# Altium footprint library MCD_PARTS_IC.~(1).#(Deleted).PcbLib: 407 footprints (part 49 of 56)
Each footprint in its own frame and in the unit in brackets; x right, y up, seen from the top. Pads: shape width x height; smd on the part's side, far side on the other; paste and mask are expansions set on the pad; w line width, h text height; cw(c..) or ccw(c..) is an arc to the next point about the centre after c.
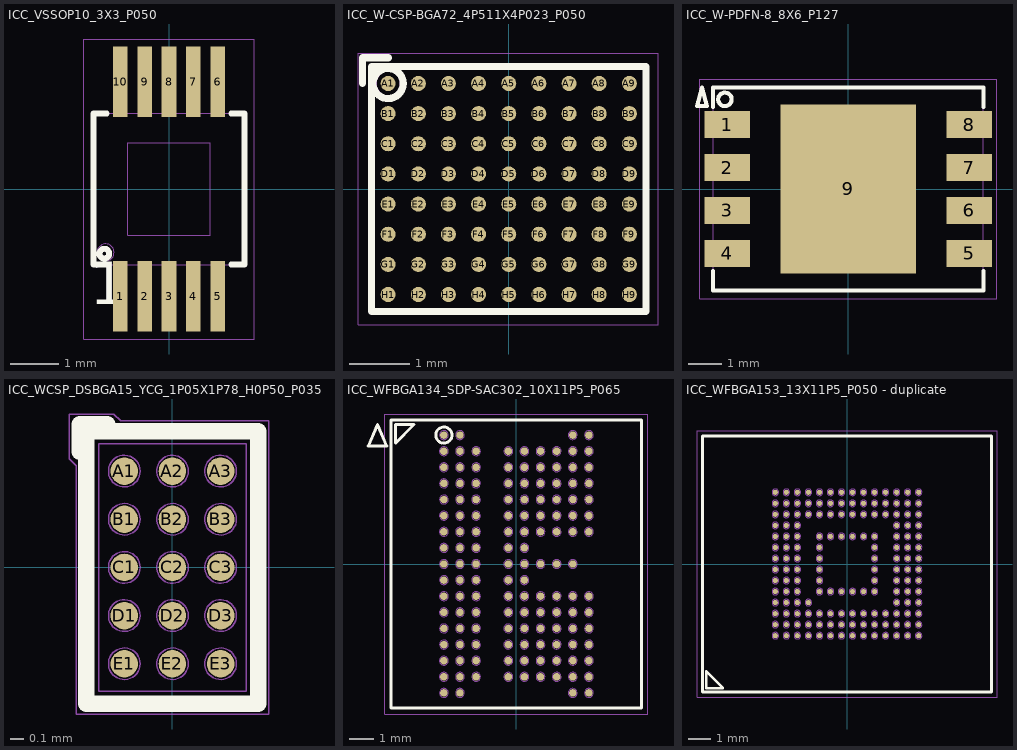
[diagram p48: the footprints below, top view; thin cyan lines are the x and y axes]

## ICC_VSSOP10_3X3_P050 [mm] "MCD-02208"
height 1.1
pads (10):
  rect 0.3x1.45 smd paste+0 mask+0.05: 1(-1,-2.2) 2(-0.5,-2.2) 3(0,-2.2) 4(0.5,-2.2) 5(1,-2.2) 6(1,2.2) 7(0.5,2.2) 8(0,2.2) 9(-0.5,2.2) 10(-1,2.2)
Top Overlay:
  circle w0.12: c-1.325,-1.325 r0.1
  lines w0.12: -1.275,-1.55 -1.55,-1.55 -1.55,1.55 -1.275,1.55 ; 1.275,-1.55 1.55,-1.55 1.55,1.55 1.275,1.55
  text "1" at -1.625,-2.65 h1.5
M14-Top Assembly:
  circle w0.01: c-1.3,-1.3 r0.175
  lines w0.01: -1.125,-1.55 -1.125,-2.5 -0.875,-2.5 -0.875,-1.55 ; -1.125,1.55 -1.125,2.5 -0.875,2.5 -0.875,1.55 ; -0.625,-1.55 -0.625,-2.5 -0.375,-2.5 -0.375,-1.55 ; -0.625,1.55 -0.625,2.5 -0.375,2.5 -0.375,1.55 ; -0.125,-1.55 -0.125,-2.5 0.125,-2.5 0.125,-1.55 ; -0.125,1.55 -0.125,2.5 0.125,2.5 0.125,1.55 ; 0.375,-1.55 0.375,-2.5 0.625,-2.5 0.625,-1.55 ; 0.375,1.55 0.375,2.5 0.625,2.5 0.625,1.55 ; 0.875,-1.55 0.875,-2.5 1.125,-2.5 1.125,-1.55 ; 0.875,1.55 0.875,2.5 1.125,2.5 1.125,1.55 ; -1.55,-1.55 1.55,-1.55 1.55,1.55 -1.55,1.55 -1.55,-1.55 ; -0.85,-0.95 0.85,-0.95 0.85,0.95 -0.85,0.95 -0.85,-0.95
  text "1" at -1.125,-2.35 h1
  text "5" at 0.8,-2.35 h1
  text "6" at 0.8,1.75 h1
  text "10" at -1.425,1.75 h1
  text "'.Designator'" at -2,-0.5 h0.75
M16-Top Courtyard:
  lines w0.01: -1.75,-3.075 -1.75,3.075 1.75,3.075 1.75,-3.075 -1.75,-3.075
3D body "User Library-DGS0010A.STEP": height 1.1, standoff 0, extent -1.5,-2.462 1.5,2.463
3D body: height 1.1, standoff 0, extent -1.549,-1.549 1.549,1.549

## ICC_W-CSP-BGA72_4P511X4P023_P050 [mm]
height 0.785
pads (72):
  round 0.25 smd mask+0.05: A1(-2,1.75) A2(-1.5,1.75) A3(-1,1.75) A4(-0.5,1.75) A5(0,1.75) A6(0.5,1.75) A7(1,1.75) A8(1.5,1.75) A9(2,1.75) B1(-2,1.25) B2(-1.5,1.25) B3(-1,1.25) B4(-0.5,1.25) B5(0,1.25) B6(0.5,1.25) B7(1,1.25) B8(1.5,1.25) B9(2,1.25) C1(-2,0.75) C2(-1.5,0.75) C3(-1,0.75) C4(-0.5,0.75) C5(0,0.75) C6(0.5,0.75) C7(1,0.75) C8(1.5,0.75) C9(2,0.75) D1(-2,0.25) D2(-1.5,0.25) D3(-1,0.25) D4(-0.5,0.25) D5(0,0.25) D6(0.5,0.25) D7(1,0.25) D8(1.5,0.25) D9(2,0.25) E1(-2,-0.25) E2(-1.5,-0.25) E3(-1,-0.25) E4(-0.5,-0.25) E5(0,-0.25) E6(0.5,-0.25) E7(1,-0.25) E8(1.5,-0.25) E9(2,-0.25) F1(-2,-0.75) F2(-1.5,-0.75) F3(-1,-0.75) F4(-0.5,-0.75) F5(0,-0.75) F6(0.5,-0.75) F7(1,-0.75) F8(1.5,-0.75) F9(2,-0.75) G1(-2,-1.25) G2(-1.5,-1.25) G3(-1,-1.25) G4(-0.5,-1.25) G5(0,-1.25) G6(0.5,-1.25) G7(1,-1.25) G8(1.5,-1.25) G9(2,-1.25) H1(-2,-1.75) H2(-1.5,-1.75) H3(-1,-1.75) H4(-0.5,-1.75) H5(0,-1.75) H6(0.5,-1.75) H7(1,-1.75) H8(1.5,-1.75) H9(2,-1.75)
Top Overlay:
  circle w0.12: c-2,1.75 r0.25
  lines w0.12: -2.425,1.75 -2.425,2.175 -2,2.175 ; -2.275,-2.031 2.275,-2.031 2.275,2.031 -2.275,2.031 -2.275,-2.031
M14-Top Assembly:
  circle w0.01: c-2,1.75 r0.2
  lines w0.01: -2.275,-2.031 2.275,-2.031 2.275,2.031 -2.275,2.031 -2.275,-2.031
  text "'.Designator'" at -2,-0.5 h0.75
M16-Top Courtyard:
  lines w0.01: -2.5,-2.25 -2.5,2.225 -2.5,2.25 -2.475,2.25 2.475,2.25 2.475,-2.25 -2.5,-2.25
3D body: height 0.78, standoff 0, extent -2.28,-2.036 2.28,2.036

## ICC_W-PDFN-8_8X6_P127 [mm]
height 0.8
pads (9):
  rect 1.35x0.8 smd mask+0.05: 1(-3.575,1.905) 2(-3.575,0.635) 3(-3.575,-0.635) 4(-3.575,-1.905) 5(3.575,-1.905) 6(3.575,-0.635) 7(3.575,0.635) 8(3.575,1.905)
  rect 4x5 smd mask+0.05: 9(0,0)
Top Overlay:
  circle w0.12: c-3.65,2.65 r0.2
  lines w0.12: -4,-2.425 -4,-3 4,-3 4,-2.425 ; -4,2.425 -4,3 4,3 4,2.425 ; -4.475,2.45 -4.325,3 -4.175,2.45 -4.475,2.45
M14-Top Assembly:
  circle w0.01: c-3.675,2.675 r0.2
  lines w0.01: -4,-2.16 -3.4,-2.16 -3.4,-1.65 -4,-1.65 ; -4,-0.89 -3.4,-0.89 -3.4,-0.38 -4,-0.38 ; -4,0.38 -3.4,0.38 -3.4,0.89 -4,0.89 ; -4,1.65 -3.4,1.65 -3.4,2.16 -4,2.16 ; 4,-2.16 3.4,-2.16 3.4,-1.65 4,-1.65 ; 4,-0.89 3.4,-0.89 3.4,-0.38 4,-0.38 ; 4,0.38 3.4,0.38 3.4,0.89 4,0.89 ; 4,1.65 3.4,1.65 3.4,2.16 4,2.16 ; -4,-3 -4,3 4,3 4,-3 -4,-3 ; -1.75,-2.2 -1.75,2.2 1.75,2.2 1.75,-2.2 -1.75,-2.2
  text "'.Designator'" at -2,-0.5 h0.75
  text "1" at -3.325,1.45 h1.5
  text "4" at -3.325,-2.375 h1.5
  text "5" at 2.675,-2.375 h1.5
  text "8" at 2.675,1.425 h1.5
M16-Top Courtyard:
  lines w0.01: -4.4,-3.25 4.4,-3.25 4.4,3.25 -4.4,3.25 -4.4,3.05 -4.4,-3.25
3D body: height 0.81, standoff 0.8, extent -3.697,1.901 -2.9,2.699
3D body: height 0.8, standoff 0, extent -4.005,-3.005 4.005,3.005

## ICC_WCSP_DSBGA15_YCG_1P05X1P78_H0P50_P035 [mm] "MCD-02471"
height 0.5
pads (15):
  round 0.2 smd mask+0.032: A1(-0.35,0.7) A2(0,0.7) A3(0.35,0.7) B1(-0.35,0.35) B2(0,0.35) B3(0.35,0.35) C1(-0.35,0) C2(0,0) C3(0.35,0) D1(-0.35,-0.35) D2(0,-0.35) D3(0.35,-0.35) E1(-0.35,-0.7) E2(0,-0.7) E3(0.35,-0.7)
Top Overlay:
  lines w0.12: -0.675,0.84 -0.675,1.04 -0.475,1.04 ; -0.475,0.99 -0.625,0.99 ; -0.625,0.99 0.625,0.99 0.625,-0.99 -0.625,-0.99 -0.625,0.99
Top Paste:
  drawing of 15 lines, arcs and shapes, not listed
M14-Top Assembly:
  circle w0.01: c0.35,-0.7 r0.115
  circle w0.01: c0,-0.7 r0.115
  circle w0.01: c-0.35,-0.7 r0.115
  circle w0.01: c0.35,-0.35 r0.115
  circle w0.01: c0,-0.35 r0.115
  circle w0.01: c-0.35,-0.35 r0.115
  circle w0.01: c0.35,0 r0.115
  circle w0.01: c0,0 r0.115
  circle w0.01: c-0.35,0 r0.115
  circle w0.01: c0.35,0.35 r0.115
  circle w0.01: c0,0.35 r0.115
  circle w0.01: c-0.35,0.35 r0.115
  circle w0.01: c0.35,0.7 r0.115
  circle w0.01: c0,0.7 r0.115
  circle w0.01: c-0.35,0.7 r0.115
  lines w0.01: -0.535,-0.9 -0.535,0.9 -0.466,0.9 0.535,0.9 0.535,-0.9 -0.535,-0.9
  text "E3" at 0.227,-0.777 h0.25
  text "E2" at -0.122,-0.777 h0.25
  text "E1" at -0.457,-0.777 h0.25
  text "D3" at 0.221,-0.427 h0.25
  text "D2" at -0.129,-0.427 h0.25
  text "D1" at -0.464,-0.427 h0.25
  text "C3" at 0.218,-0.079 h0.25
  text "C2" at -0.132,-0.079 h0.25
  text "C1" at -0.467,-0.079 h0.25
  text "B3" at 0.226,0.273 h0.25
  text "B2" at -0.123,0.273 h0.25
  text "B1" at -0.458,0.273 h0.25
  text "A3" at 0.218,0.623 h0.25
  text "A2" at -0.131,0.623 h0.25
  text "A1" at -0.467,0.623 h0.25
  text "'.Designator'" at -2,-0.5 h0.75
M16-Top Courtyard:
  lines w0.01: -0.75,0.79 -0.75,1.115 -0.425,1.115 -0.375,1.065 0.7,1.065 0.7,-1.065 -0.7,-1.065 -0.7,0.74 -0.75,0.79
3D body: height 0.24, standoff -0.02, extent 0.224,-0.828 0.476,-0.572
3D body: height 0.24, standoff -0.02, extent -0.126,-0.828 0.126,-0.572
3D body: height 0.24, standoff -0.02, extent -0.476,-0.828 -0.224,-0.572
3D body: height 0.24, standoff -0.02, extent 0.224,-0.478 0.476,-0.222
3D body: height 0.24, standoff -0.02, extent -0.126,-0.478 0.126,-0.222
3D body: height 0.24, standoff -0.02, extent -0.476,-0.478 -0.224,-0.222
3D body: height 0.24, standoff -0.02, extent 0.224,-0.128 0.476,0.128
3D body: height 0.24, standoff -0.02, extent -0.126,-0.128 0.126,0.128
3D body: height 0.24, standoff -0.02, extent -0.476,-0.128 -0.224,0.128
3D body: height 0.24, standoff -0.02, extent 0.224,0.222 0.476,0.478
3D body: height 0.24, standoff -0.02, extent -0.126,0.222 0.126,0.478
3D body: height 0.24, standoff -0.02, extent -0.476,0.222 -0.224,0.478
3D body: height 0.24, standoff -0.02, extent 0.224,0.572 0.476,0.828
3D body: height 0.24, standoff -0.02, extent -0.126,0.572 0.126,0.828
3D body: height 0.51, standoff 0.5, extent -0.535,0.5 -0.3,0.9
3D body: height 0.24, standoff -0.02, extent -0.476,0.572 -0.224,0.828
3D body: height 0.5, standoff 0.13, extent -0.535,-0.9 0.535,0.9

## ICC_WFBGA134_SDP-SAC302_10X11P5_P065 [mm] "IPC"
height 0.75
pads (134):
  round 0.3 smd mask+0.05: A1(-2.925,5.2) A2(-2.275,5.2) A9(2.275,5.2) A10(2.925,5.2) B1(-2.925,4.55) B2(-2.275,4.55) B3(-1.625,4.55) B5(-0.325,4.55) B6(0.325,4.55) B7(0.975,4.55) B8(1.625,4.55) B9(2.275,4.55) B10(2.925,4.55) C1(-2.925,3.9) C2(-2.275,3.9) C3(-1.625,3.9) C5(-0.325,3.9) C6(0.325,3.9) C7(0.975,3.9) C8(1.625,3.9) C9(2.275,3.9) C10(2.925,3.9) D1(-2.925,3.25) D2(-2.275,3.25) D3(-1.625,3.25) D5(-0.325,3.25) D6(0.325,3.25) D7(0.975,3.25) D8(1.625,3.25) D9(2.275,3.25) D10(2.925,3.25) E1(-2.925,2.6) E2(-2.275,2.6) E3(-1.625,2.6) E5(-0.325,2.6) E6(0.325,2.6) E7(0.975,2.6) E8(1.625,2.6) E9(2.275,2.6) E10(2.925,2.6) F1(-2.925,1.95) F2(-2.275,1.95) F3(-1.625,1.95) F5(-0.325,1.95) F6(0.325,1.95) F7(0.975,1.95) F8(1.625,1.95) F9(2.275,1.95) F10(2.925,1.95) G1(-2.925,1.3) G2(-2.275,1.3) G3(-1.625,1.3) G5(-0.325,1.3) G6(0.325,1.3) G7(0.975,1.3) G8(1.625,1.3) G9(2.275,1.3) G10(2.925,1.3) H1(-2.925,0.65) H2(-2.275,0.65) H3(-1.625,0.65) H5(-0.325,0.65) H6(0.325,0.65) J1(-2.925,0) J2(-2.275,0) J3(-1.625,0) J5(-0.325,0) J6(0.325,0) J7(0.975,0) J8(1.625,0) J9(2.275,0) K1(-2.925,-0.65) K2(-2.275,-0.65) K3(-1.625,-0.65) K5(-0.325,-0.65) K6(0.325,-0.65) L1(-2.925,-1.3) L2(-2.275,-1.3) L3(-1.625,-1.3) L5(-0.325,-1.3) L6(0.325,-1.3) L7(0.975,-1.3) L8(1.625,-1.3) L9(2.275,-1.3) L10(2.925,-1.3) M1(-2.925,-1.95) M2(-2.275,-1.95) M3(-1.625,-1.95) M5(-0.325,-1.95) M6(0.325,-1.95) M7(0.975,-1.95) M8(1.625,-1.95) M9(2.275,-1.95) M10(2.925,-1.95) N1(-2.925,-2.6) N2(-2.275,-2.6) N3(-1.625,-2.6) N5(-0.325,-2.6) N6(0.325,-2.6) N7(0.975,-2.6) N8(1.625,-2.6) N9(2.275,-2.6) N10(2.925,-2.6) P1(-2.925,-3.25) P2(-2.275,-3.25) P3(-1.625,-3.25) P5(-0.325,-3.25) P6(0.325,-3.25) P7(0.975,-3.25) P8(1.625,-3.25) P9(2.275,-3.25) P10(2.925,-3.25) R1(-2.925,-3.9) R2(-2.275,-3.9) R3(-1.625,-3.9) R5(-0.325,-3.9) R6(0.325,-3.9) R7(0.975,-3.9) R8(1.625,-3.9) R9(2.275,-3.9) R10(2.925,-3.9) T1(-2.925,-4.55) T2(-2.275,-4.55) T3(-1.625,-4.55) T5(-0.325,-4.55) T6(0.325,-4.55) T7(0.975,-4.55) T8(1.625,-4.55) T9(2.275,-4.55) T10(2.925,-4.55) U1(-2.925,-5.2) U2(-2.275,-5.2) U9(2.275,-5.2) U10(2.925,-5.2)
Top Overlay:
  circle w0.12: c-2.925,5.2 r0.325
  lines w0.12: -4.125,5.625 -4.875,4.875 -4.875,5.625 -4.125,5.625 ; -4.125,5.625 -4.125,5.625 ; -5.975,4.75 -5.225,4.75 -5.6,5.625 -5.975,4.75 ; -5.05,-5.8 5.05,-5.8 5.05,5.8 -5.05,5.8 -5.05,-5.8
M14-Top Assembly:
  circle w0.01: c-2.925,-5.2 r0.18
  circle w0.01: c-2.275,-5.2 r0.18
  circle w0.01: c2.275,-5.2 r0.18
  circle w0.01: c2.925,-5.2 r0.18
  circle w0.01: c-2.925,-4.55 r0.18
  circle w0.01: c-2.275,-4.55 r0.18
  circle w0.01: c-1.625,-4.55 r0.18
  circle w0.01: c-0.325,-4.55 r0.18
  circle w0.01: c0.325,-4.55 r0.18
  circle w0.01: c0.975,-4.55 r0.18
  circle w0.01: c1.625,-4.55 r0.18
  circle w0.01: c2.275,-4.55 r0.18
  circle w0.01: c2.925,-4.55 r0.18
  circle w0.01: c-2.925,-3.9 r0.18
  circle w0.01: c-2.275,-3.9 r0.18
  circle w0.01: c-1.625,-3.9 r0.18
  circle w0.01: c-0.325,-3.9 r0.18
  circle w0.01: c0.325,-3.9 r0.18
  circle w0.01: c0.975,-3.9 r0.18
  circle w0.01: c1.625,-3.9 r0.18
  circle w0.01: c2.275,-3.9 r0.18
  circle w0.01: c2.925,-3.9 r0.18
  circle w0.01: c-2.925,-3.25 r0.18
  circle w0.01: c-2.275,-3.25 r0.18
  circle w0.01: c-1.625,-3.25 r0.18
  circle w0.01: c-0.325,-3.25 r0.18
  circle w0.01: c0.325,-3.25 r0.18
  circle w0.01: c0.975,-3.25 r0.18
  circle w0.01: c1.625,-3.25 r0.18
  circle w0.01: c2.275,-3.25 r0.18
  circle w0.01: c2.925,-3.25 r0.18
  circle w0.01: c-2.925,-2.6 r0.18
  circle w0.01: c-2.275,-2.6 r0.18
  circle w0.01: c-1.625,-2.6 r0.18
  circle w0.01: c-0.325,-2.6 r0.18
  circle w0.01: c0.325,-2.6 r0.18
  circle w0.01: c0.975,-2.6 r0.18
  circle w0.01: c1.625,-2.6 r0.18
  circle w0.01: c2.275,-2.6 r0.18
  circle w0.01: c2.925,-2.6 r0.18
  circle w0.01: c-2.925,-1.95 r0.18
  circle w0.01: c-2.275,-1.95 r0.18
  circle w0.01: c-1.625,-1.95 r0.18
  circle w0.01: c-0.325,-1.95 r0.18
  circle w0.01: c0.325,-1.95 r0.18
  circle w0.01: c0.975,-1.95 r0.18
  circle w0.01: c1.625,-1.95 r0.18
  circle w0.01: c2.275,-1.95 r0.18
  circle w0.01: c2.925,-1.95 r0.18
  circle w0.01: c-2.925,-1.3 r0.18
  circle w0.01: c-2.275,-1.3 r0.18
  circle w0.01: c-1.625,-1.3 r0.18
  circle w0.01: c-0.325,-1.3 r0.18
  circle w0.01: c0.325,-1.3 r0.18
  circle w0.01: c0.975,-1.3 r0.18
  circle w0.01: c1.625,-1.3 r0.18
  circle w0.01: c2.275,-1.3 r0.18
  circle w0.01: c2.925,-1.3 r0.18
  circle w0.01: c-2.925,-0.65 r0.18
  circle w0.01: c-2.275,-0.65 r0.18
  circle w0.01: c-1.625,-0.65 r0.18
  circle w0.01: c-0.325,-0.65 r0.18
  circle w0.01: c0.325,-0.65 r0.18
  circle w0.01: c-2.925,0 r0.18
  circle w0.01: c-2.275,0 r0.18
  circle w0.01: c-1.625,0 r0.18
  circle w0.01: c-0.325,0 r0.18
  circle w0.01: c0.325,0 r0.18
  circle w0.01: c0.975,0 r0.18
  circle w0.01: c1.625,0 r0.18
  circle w0.01: c2.275,0 r0.18
  circle w0.01: c-2.925,0.65 r0.18
  circle w0.01: c-2.275,0.65 r0.18
  circle w0.01: c-1.625,0.65 r0.18
  circle w0.01: c-0.325,0.65 r0.18
  circle w0.01: c0.325,0.65 r0.18
  circle w0.01: c-2.925,1.3 r0.18
  circle w0.01: c-2.275,1.3 r0.18
  circle w0.01: c-1.625,1.3 r0.18
  circle w0.01: c-0.325,1.3 r0.18
  circle w0.01: c0.325,1.3 r0.18
  circle w0.01: c0.975,1.3 r0.18
  circle w0.01: c1.625,1.3 r0.18
  circle w0.01: c2.275,1.3 r0.18
  circle w0.01: c2.925,1.3 r0.18
  circle w0.01: c-2.925,1.95 r0.18
  circle w0.01: c-2.275,1.95 r0.18
  circle w0.01: c-1.625,1.95 r0.18
  circle w0.01: c-0.325,1.95 r0.18
  circle w0.01: c0.325,1.95 r0.18
  circle w0.01: c0.975,1.95 r0.18
  circle w0.01: c1.625,1.95 r0.18
  circle w0.01: c2.275,1.95 r0.18
  circle w0.01: c2.925,1.95 r0.18
  circle w0.01: c-2.925,2.6 r0.18
  circle w0.01: c-2.275,2.6 r0.18
  circle w0.01: c-1.625,2.6 r0.18
  circle w0.01: c-0.325,2.6 r0.18
  circle w0.01: c0.325,2.6 r0.18
  circle w0.01: c0.975,2.6 r0.18
  circle w0.01: c1.625,2.6 r0.18
  circle w0.01: c2.275,2.6 r0.18
  circle w0.01: c2.925,2.6 r0.18
  circle w0.01: c-2.925,3.25 r0.18
  circle w0.01: c-2.275,3.25 r0.18
  circle w0.01: c-1.625,3.25 r0.18
  circle w0.01: c-0.325,3.25 r0.18
  circle w0.01: c0.325,3.25 r0.18
  circle w0.01: c0.975,3.25 r0.18
  circle w0.01: c1.625,3.25 r0.18
  circle w0.01: c2.275,3.25 r0.18
  circle w0.01: c2.925,3.25 r0.18
  circle w0.01: c-2.925,3.9 r0.18
  circle w0.01: c-2.275,3.9 r0.18
  circle w0.01: c-1.625,3.9 r0.18
  circle w0.01: c-0.325,3.9 r0.18
  circle w0.01: c0.325,3.9 r0.18
  circle w0.01: c0.975,3.9 r0.18
  circle w0.01: c1.625,3.9 r0.18
  circle w0.01: c2.275,3.9 r0.18
  circle w0.01: c2.925,3.9 r0.18
  circle w0.01: c2.925,4.55 r0.18
  circle w0.01: c2.275,4.55 r0.18
  circle w0.01: c1.625,4.55 r0.18
  circle w0.01: c0.975,4.55 r0.18
  circle w0.01: c0.325,4.55 r0.18
  circle w0.01: c-0.325,4.55 r0.18
  circle w0.01: c-1.625,4.55 r0.18
  circle w0.01: c-2.275,4.55 r0.18
  circle w0.01: c-2.925,4.55 r0.18
  circle w0.01: c2.925,5.2 r0.18
  circle w0.01: c2.275,5.2 r0.18
  circle w0.01: c-2.275,5.2 r0.18
  circle w0.01: c-2.925,5.2 r0.18
  lines w0.01: -5.05,-5.8 -5.05,5.8 5.05,5.8 5.05,-5.8 -5.05,-5.8
  text "A" at -3.608,5.038 h0.5
  text "B" at -3.608,4.387 h0.5
  text "C" at -3.608,3.738 h0.5
  text "D" at -3.608,3.087 h0.5
  text "E" at -3.608,2.438 h0.5
  text "F" at -3.608,1.787 h0.5
  text "G" at -3.608,1.138 h0.5
  text "H" at -3.608,0.487 h0.5
  text "J" at -3.608,-0.162 h0.5
  text "K" at -3.608,-0.813 h0.5
  text "L" at -3.608,-1.462 h0.5
  text "M" at -3.608,-2.113 h0.5
  text "N" at -3.608,-2.762 h0.5
  text "P" at -3.608,-3.413 h0.5
  text "R" at -3.608,-4.062 h0.5
  text "T" at -3.608,-4.713 h0.5
  text "U" at -3.608,-5.362 h0.5
  text "1" at -3.023,5.427 h0.5
  text "2" at -2.372,5.427 h0.5
  text "3" at -1.723,5.427 h0.5
  text "4" at -1.072,5.427 h0.5
  text "5" at -0.423,5.427 h0.5
  text "6" at 0.228,5.427 h0.5
  text "7" at 0.877,5.427 h0.5
  text "8" at 1.528,5.427 h0.5
  text "9" at 2.177,5.427 h0.5
  text "10" at 2.698,5.427 h0.5
  text "'.Designator'" at 0.5,0 h0.75
M16-Top Courtyard:
  lines w0.01: -5.3,-6.05 5.3,-6.05 5.3,6.05 -5.3,6.05 -5.3,-6.05
3D body: height 0.75, standoff 0.28, extent -5.05,-5.8 5.05,5.8
3D body: height 0.34, standoff -0.02, extent 2.754,5.023 3.105,5.377
3D body: height 0.34, standoff -0.02, extent 2.104,5.023 2.455,5.377
3D body: height 0.34, standoff -0.02, extent -2.446,5.023 -2.095,5.377
3D body: height 0.34, standoff -0.02, extent -3.096,5.023 -2.745,5.377
3D body: height 0.34, standoff -0.02, extent -3.096,4.373 -2.745,4.727
3D body: height 0.34, standoff -0.02, extent -2.446,4.373 -2.095,4.727
3D body: height 0.34, standoff -0.02, extent -1.796,4.373 -1.445,4.727
3D body: height 0.34, standoff -0.02, extent -0.496,4.373 -0.145,4.727
3D body: height 0.34, standoff -0.02, extent 0.154,4.373 0.505,4.727
3D body: height 0.34, standoff -0.02, extent 0.804,4.373 1.155,4.727
3D body: height 0.34, standoff -0.02, extent 1.454,4.373 1.805,4.727
3D body: height 0.34, standoff -0.02, extent 2.104,4.373 2.455,4.727
3D body: height 0.34, standoff -0.02, extent 2.754,4.373 3.105,4.727
3D body: height 0.34, standoff -0.02, extent 2.754,3.723 3.105,4.077
3D body: height 0.34, standoff -0.02, extent 2.104,3.723 2.455,4.077
3D body: height 0.34, standoff -0.02, extent 1.454,3.723 1.805,4.077
3D body: height 0.34, standoff -0.02, extent 0.804,3.723 1.155,4.077
3D body: height 0.34, standoff -0.02, extent 0.154,3.723 0.505,4.077
3D body: height 0.34, standoff -0.02, extent -0.496,3.723 -0.145,4.077
3D body: height 0.34, standoff -0.02, extent -1.796,3.723 -1.445,4.077
3D body: height 0.34, standoff -0.02, extent -2.446,3.723 -2.095,4.077
3D body: height 0.34, standoff -0.02, extent -3.096,3.723 -2.745,4.077
3D body: height 0.34, standoff -0.02, extent 2.754,3.073 3.105,3.427
3D body: height 0.34, standoff -0.02, extent 2.104,3.073 2.455,3.427
3D body: height 0.34, standoff -0.02, extent 1.454,3.073 1.805,3.427
3D body: height 0.34, standoff -0.02, extent 0.804,3.073 1.155,3.427
3D body: height 0.34, standoff -0.02, extent 0.154,3.073 0.505,3.427
3D body: height 0.34, standoff -0.02, extent -0.496,3.073 -0.145,3.427
3D body: height 0.34, standoff -0.02, extent -1.796,3.073 -1.445,3.427
3D body: height 0.34, standoff -0.02, extent -2.446,3.073 -2.095,3.427
3D body: height 0.34, standoff -0.02, extent -3.096,3.073 -2.745,3.427
3D body: height 0.34, standoff -0.02, extent 2.754,2.423 3.105,2.777
3D body: height 0.34, standoff -0.02, extent 2.104,2.423 2.455,2.777
3D body: height 0.34, standoff -0.02, extent 1.454,2.423 1.805,2.777
3D body: height 0.34, standoff -0.02, extent 0.804,2.423 1.155,2.777
3D body: height 0.34, standoff -0.02, extent 0.154,2.423 0.505,2.777
3D body: height 0.34, standoff -0.02, extent -0.496,2.423 -0.145,2.777
3D body: height 0.34, standoff -0.02, extent -1.796,2.423 -1.445,2.777
3D body: height 0.34, standoff -0.02, extent -2.446,2.423 -2.095,2.777
3D body: height 0.34, standoff -0.02, extent -3.096,2.423 -2.745,2.777
3D body: height 0.34, standoff -0.02, extent 2.754,1.773 3.105,2.127
3D body: height 0.34, standoff -0.02, extent 2.104,1.773 2.455,2.127
3D body: height 0.34, standoff -0.02, extent 1.454,1.773 1.805,2.127
3D body: height 0.34, standoff -0.02, extent 0.804,1.773 1.155,2.127
3D body: height 0.34, standoff -0.02, extent 0.154,1.773 0.505,2.127
3D body: height 0.34, standoff -0.02, extent -0.496,1.773 -0.145,2.127
3D body: height 0.34, standoff -0.02, extent -1.796,1.773 -1.445,2.127
3D body: height 0.34, standoff -0.02, extent -2.446,1.773 -2.095,2.127
3D body: height 0.34, standoff -0.02, extent -3.096,1.773 -2.745,2.127
3D body: height 0.34, standoff -0.02, extent 2.754,1.123 3.105,1.477
3D body: height 0.34, standoff -0.02, extent 2.104,1.123 2.455,1.477
3D body: height 0.34, standoff -0.02, extent 1.454,1.123 1.805,1.477
3D body: height 0.34, standoff -0.02, extent 0.804,1.123 1.155,1.477
3D body: height 0.34, standoff -0.02, extent 0.154,1.123 0.505,1.477
3D body: height 0.34, standoff -0.02, extent -0.496,1.123 -0.145,1.477
3D body: height 0.34, standoff -0.02, extent -1.796,1.123 -1.445,1.477
3D body: height 0.34, standoff -0.02, extent -2.446,1.123 -2.095,1.477
3D body: height 0.34, standoff -0.02, extent -3.096,1.123 -2.745,1.477
3D body: height 0.34, standoff -0.02, extent 2.754,-1.477 3.105,-1.123
3D body: height 0.34, standoff -0.02, extent 2.104,-1.477 2.455,-1.123
3D body: height 0.34, standoff -0.02, extent 1.454,-1.477 1.805,-1.123
3D body: height 0.34, standoff -0.02, extent 0.804,-1.477 1.155,-1.123
3D body: height 0.34, standoff -0.02, extent 0.154,-1.477 0.505,-1.123
3D body: height 0.34, standoff -0.02, extent -0.496,-1.477 -0.145,-1.123
3D body: height 0.34, standoff -0.02, extent -1.796,-1.477 -1.445,-1.123
3D body: height 0.34, standoff -0.02, extent -2.446,-1.477 -2.095,-1.123
3D body: height 0.34, standoff -0.02, extent -3.096,-1.477 -2.745,-1.123
3D body: height 0.34, standoff -0.02, extent 2.754,-2.127 3.105,-1.773
3D body: height 0.34, standoff -0.02, extent 2.104,-2.127 2.455,-1.773
3D body: height 0.34, standoff -0.02, extent 1.454,-2.127 1.805,-1.773
3D body: height 0.34, standoff -0.02, extent 0.804,-2.127 1.155,-1.773
3D body: height 0.34, standoff -0.02, extent 0.154,-2.127 0.505,-1.773
3D body: height 0.34, standoff -0.02, extent -0.496,-2.127 -0.145,-1.773
3D body: height 0.34, standoff -0.02, extent -1.796,-2.127 -1.445,-1.773
3D body: height 0.34, standoff -0.02, extent -2.446,-2.127 -2.095,-1.773
3D body: height 0.34, standoff -0.02, extent -3.096,-2.127 -2.745,-1.773
3D body: height 0.34, standoff -0.02, extent 2.754,-2.777 3.105,-2.423
3D body: height 0.34, standoff -0.02, extent 2.104,-2.777 2.455,-2.423
3D body: height 0.34, standoff -0.02, extent 1.454,-2.777 1.805,-2.423
3D body: height 0.34, standoff -0.02, extent 0.804,-2.777 1.155,-2.423
3D body: height 0.34, standoff -0.02, extent 0.154,-2.777 0.505,-2.423
3D body: height 0.34, standoff -0.02, extent -0.496,-2.777 -0.145,-2.423
3D body: height 0.34, standoff -0.02, extent -1.796,-2.777 -1.445,-2.423
3D body: height 0.34, standoff -0.02, extent -2.446,-2.777 -2.095,-2.423
3D body: height 0.34, standoff -0.02, extent -3.096,-2.777 -2.745,-2.423
3D body: height 0.34, standoff -0.02, extent 2.754,-3.427 3.105,-3.073
3D body: height 0.34, standoff -0.02, extent 2.104,-3.427 2.455,-3.073
3D body: height 0.34, standoff -0.02, extent 1.454,-3.427 1.805,-3.073
3D body: height 0.34, standoff -0.02, extent 0.804,-3.427 1.155,-3.073
3D body: height 0.34, standoff -0.02, extent 0.154,-3.427 0.505,-3.073
3D body: height 0.34, standoff -0.02, extent -0.496,-3.427 -0.145,-3.073
3D body: height 0.34, standoff -0.02, extent -1.796,-3.427 -1.445,-3.073
3D body: height 0.34, standoff -0.02, extent -2.446,-3.427 -2.095,-3.073
3D body: height 0.34, standoff -0.02, extent -3.096,-3.427 -2.745,-3.073
3D body: height 0.34, standoff -0.02, extent 2.754,-4.077 3.105,-3.723
3D body: height 0.34, standoff -0.02, extent 2.104,-4.077 2.455,-3.723
3D body: height 0.34, standoff -0.02, extent 1.454,-4.077 1.805,-3.723
3D body: height 0.34, standoff -0.02, extent 0.804,-4.077 1.155,-3.723
3D body: height 0.34, standoff -0.02, extent 0.154,-4.077 0.505,-3.723
3D body: height 0.34, standoff -0.02, extent -0.496,-4.077 -0.145,-3.723
3D body: height 0.34, standoff -0.02, extent -1.796,-4.077 -1.445,-3.723
3D body: height 0.34, standoff -0.02, extent -2.446,-4.077 -2.095,-3.723
3D body: height 0.34, standoff -0.02, extent -3.096,-4.077 -2.745,-3.723
3D body: height 0.34, standoff -0.02, extent 2.754,-4.727 3.105,-4.373
3D body: height 0.34, standoff -0.02, extent 2.104,-4.727 2.455,-4.373
3D body: height 0.34, standoff -0.02, extent 1.454,-4.727 1.805,-4.373
3D body: height 0.34, standoff -0.02, extent 0.804,-4.727 1.155,-4.373
3D body: height 0.34, standoff -0.02, extent 0.154,-4.727 0.505,-4.373
3D body: height 0.34, standoff -0.02, extent -0.496,-4.727 -0.145,-4.373
3D body: height 0.34, standoff -0.02, extent -1.796,-4.727 -1.445,-4.373
3D body: height 0.34, standoff -0.02, extent -2.446,-4.727 -2.095,-4.373
3D body: height 0.34, standoff -0.02, extent -3.096,-4.727 -2.745,-4.373
3D body: height 0.34, standoff -0.02, extent -3.096,0.473 -2.745,0.827
3D body: height 0.34, standoff -0.02, extent -2.446,0.473 -2.095,0.827
3D body: height 0.34, standoff -0.02, extent -1.796,0.473 -1.445,0.827
3D body: height 0.34, standoff -0.02, extent -0.496,0.473 -0.145,0.827
3D body: height 0.34, standoff -0.02, extent 0.154,0.473 0.505,0.827
3D body: height 0.34, standoff -0.02, extent -3.096,-0.177 -2.745,0.177
3D body: height 0.34, standoff -0.02, extent -2.446,-0.177 -2.095,0.177
3D body: height 0.34, standoff -0.02, extent -1.796,-0.177 -1.445,0.177
3D body: height 0.34, standoff -0.02, extent -0.496,-0.177 -0.145,0.177
3D body: height 0.34, standoff -0.02, extent 0.154,-0.177 0.505,0.177
3D body: height 0.34, standoff -0.02, extent 0.804,-0.177 1.155,0.177
3D body: height 0.34, standoff -0.02, extent 1.454,-0.177 1.805,0.177
3D body: height 0.34, standoff -0.02, extent 2.104,-0.177 2.455,0.177
3D body: height 0.34, standoff -0.02, extent -3.096,-0.827 -2.745,-0.473
3D body: height 0.34, standoff -0.02, extent -2.446,-0.827 -2.095,-0.473
3D body: height 0.34, standoff -0.02, extent -1.796,-0.827 -1.445,-0.473
3D body: height 0.34, standoff -0.02, extent -0.496,-0.827 -0.145,-0.473
3D body: height 0.34, standoff -0.02, extent 0.154,-0.827 0.505,-0.473
3D body: height 0.34, standoff -0.02, extent -3.096,-5.377 -2.745,-5.023
3D body: height 0.34, standoff -0.02, extent -2.446,-5.377 -2.095,-5.023
3D body: height 0.34, standoff -0.02, extent 2.104,-5.377 2.455,-5.023
3D body: height 0.34, standoff -0.02, extent 2.754,-5.377 3.105,-5.023
3D body: height 0.76, standoff 0.75, extent -4.747,4.901 -4.15,5.5

## ICC_WFBGA153_13X11P5_P050 - duplicate [mm] "MCD-04155"
height 0.8
pads (153):
  round 0.23 smd paste+0.025 mask+0.05: A1(-3.25,-3.25) A2(-3.25,-2.75) A3(-3.25,-2.25) A4(-3.25,-1.75) A5(-3.25,-1.25) A6(-3.25,-0.75) A7(-3.25,-0.25) A8(-3.25,0.25) A9(-3.25,0.75) A10(-3.25,1.25) A11(-3.25,1.75) A12(-3.25,2.25) A13(-3.25,2.75) A14(-3.25,3.25) B1(-2.75,-3.25) B2(-2.75,-2.75) B3(-2.75,-2.25) B4(-2.75,-1.75) B5(-2.75,-1.25) B6(-2.75,-0.75) B7(-2.75,-0.25) B8(-2.75,0.25) B9(-2.75,0.75) B10(-2.75,1.25) B11(-2.75,1.75) B12(-2.75,2.25) B13(-2.75,2.75) B14(-2.75,3.25) C1(-2.25,-3.25) C2(-2.25,-2.75) C3(-2.25,-2.25) C4(-2.25,-1.75) C5(-2.25,-1.25) C6(-2.25,-0.75) C7(-2.25,-0.25) C8(-2.25,0.25) C9(-2.25,0.75) C10(-2.25,1.25) C11(-2.25,1.75) C12(-2.25,2.25) C13(-2.25,2.75) C14(-2.25,3.25) D1(-1.75,-3.25) D2(-1.75,-2.75) D3(-1.75,-2.25) D4(-1.75,-1.75) D12(-1.75,2.25) D13(-1.75,2.75) D14(-1.75,3.25) E1(-1.25,-3.25) E2(-1.25,-2.75) E3(-1.25,-2.25) E5(-1.25,-1.25) E6(-1.25,-0.75) E7(-1.25,-0.25) E8(-1.25,0.25) E9(-1.25,0.75) E10(-1.25,1.25) E12(-1.25,2.25) E13(-1.25,2.75) E14(-1.25,3.25) F1(-0.75,-3.25) F2(-0.75,-2.75) F3(-0.75,-2.25) F5(-0.75,-1.25) F10(-0.75,1.25) F12(-0.75,2.25) F13(-0.75,2.75) F14(-0.75,3.25) G1(-0.25,-3.25) G2(-0.25,-2.75) G3(-0.25,-2.25) G5(-0.25,-1.25) G10(-0.25,1.25) G12(-0.25,2.25) G13(-0.25,2.75) G14(-0.25,3.25) H1(0.25,-3.25) H2(0.25,-2.75) H3(0.25,-2.25) H5(0.25,-1.25) H10(0.25,1.25) H12(0.25,2.25) H13(0.25,2.75) H14(0.25,3.25) J1(0.75,-3.25) J2(0.75,-2.75) J3(0.75,-2.25) J5(0.75,-1.25) J10(0.75,1.25) J12(0.75,2.25) J13(0.75,2.75) J14(0.75,3.25) K1(1.25,-3.25) K2(1.25,-2.75) K3(1.25,-2.25) K5(1.25,-1.25) K6(1.25,-0.75) K7(1.25,-0.25) K8(1.25,0.25) K9(1.25,0.75) K10(1.25,1.25) K12(1.25,2.25) K13(1.25,2.75) K14(1.25,3.25) L1(1.75,-3.25) L2(1.75,-2.75) L3(1.75,-2.25) L12(1.75,2.25) L13(1.75,2.75) L14(1.75,3.25) M1(2.25,-3.25) M2(2.25,-2.75) M3(2.25,-2.25) M4(2.25,-1.75) M5(2.25,-1.25) M6(2.25,-0.75) M7(2.25,-0.25) M8(2.25,0.25) M9(2.25,0.75) M10(2.25,1.25) M11(2.25,1.75) M12(2.25,2.25) M13(2.25,2.75) M14(2.25,3.25) N1(2.75,-3.25) N2(2.75,-2.75) N3(2.75,-2.25) N4(2.75,-1.75) N5(2.75,-1.25) N6(2.75,-0.75) N7(2.75,-0.25) N8(2.75,0.25) N9(2.75,0.75) N10(2.75,1.25) N11(2.75,1.75) N12(2.75,2.25) N13(2.75,2.75) N14(2.75,3.25) P1(3.25,-3.25) P2(3.25,-2.75) P3(3.25,-2.25) P4(3.25,-1.75) P5(3.25,-1.25) P6(3.25,-0.75) P7(3.25,-0.25) P8(3.25,0.25) P9(3.25,0.75) P10(3.25,1.25) P11(3.25,1.75) P12(3.25,2.25) P13(3.25,2.75) P14(3.25,3.25)
Top Overlay:
  lines w0.12: -6.375,-4.875 -6.375,-5.625 -5.625,-5.625 -6.375,-4.875 ; -6.375,-4.875 -6.375,-4.875 ; -6.55,-5.8 -6.55,5.8 6.55,5.8 6.55,-5.8 -6.55,-5.8
M14-Top Assembly:
  drawing of 157 lines, arcs and shapes, not listed
  text "A1" at -4.125,-3.75 h0.5
  text "'.Designator'" at 0,0 h0.75
M16-Top Courtyard:
  lines w0.01: -6.8,-6.05 -6.8,6.05 6.8,6.05 6.8,-6.05 -6.8,-6.05
3D body: height 0.8, standoff 0.28, extent -6.55,-5.8 6.55,5.8
3D body: height 0.31, standoff 0.01, extent -3.4,-3.4 -3.1,-3.1
3D body: height 0.31, standoff 0.01, extent -2.9,-3.4 -2.6,-3.1
3D body: height 0.31, standoff 0.01, extent -2.4,-3.4 -2.1,-3.1
3D body: height 0.31, standoff 0.01, extent -1.9,-3.4 -1.6,-3.1
3D body: height 0.31, standoff 0.01, extent -1.4,-3.4 -1.1,-3.1
3D body: height 0.31, standoff 0.01, extent -0.9,-3.4 -0.6,-3.1
3D body: height 0.31, standoff 0.01, extent -0.4,-3.4 -0.1,-3.1
3D body: height 0.31, standoff 0.01, extent 0.1,-3.4 0.4,-3.1
3D body: height 0.31, standoff 0.01, extent 0.6,-3.4 0.9,-3.1
3D body: height 0.31, standoff 0.01, extent 1.1,-3.4 1.4,-3.1
3D body: height 0.31, standoff 0.01, extent 1.6,-3.4 1.9,-3.1
3D body: height 0.31, standoff 0.01, extent 2.1,-3.4 2.4,-3.1
3D body: height 0.31, standoff 0.01, extent 2.6,-3.4 2.9,-3.1
3D body: height 0.31, standoff 0.01, extent 3.1,-3.4 3.4,-3.1
3D body: height 0.31, standoff 0.01, extent -3.4,-2.9 -3.1,-2.6
3D body: height 0.31, standoff 0.01, extent -2.9,-2.9 -2.6,-2.6
3D body: height 0.31, standoff 0.01, extent -2.4,-2.9 -2.1,-2.6
3D body: height 0.31, standoff 0.01, extent -1.9,-2.9 -1.6,-2.6
3D body: height 0.31, standoff 0.01, extent -1.4,-2.9 -1.1,-2.6
3D body: height 0.31, standoff 0.01, extent -0.9,-2.9 -0.6,-2.6
3D body: height 0.31, standoff 0.01, extent -0.4,-2.9 -0.1,-2.6
3D body: height 0.31, standoff 0.01, extent 0.1,-2.9 0.4,-2.6
3D body: height 0.31, standoff 0.01, extent 0.6,-2.9 0.9,-2.6
3D body: height 0.31, standoff 0.01, extent 1.1,-2.9 1.4,-2.6
3D body: height 0.31, standoff 0.01, extent 1.6,-2.9 1.9,-2.6
3D body: height 0.31, standoff 0.01, extent 2.1,-2.9 2.4,-2.6
3D body: height 0.31, standoff 0.01, extent 2.6,-2.9 2.9,-2.6
3D body: height 0.31, standoff 0.01, extent 3.1,-2.9 3.4,-2.6
3D body: height 0.31, standoff 0.01, extent -3.4,-2.4 -3.1,-2.1
3D body: height 0.31, standoff 0.01, extent -2.9,-2.4 -2.6,-2.1
3D body: height 0.31, standoff 0.01, extent -2.4,-2.4 -2.1,-2.1
3D body: height 0.31, standoff 0.01, extent -1.9,-2.4 -1.6,-2.1
3D body: height 0.31, standoff 0.01, extent -1.4,-2.4 -1.1,-2.1
3D body: height 0.31, standoff 0.01, extent -0.9,-2.4 -0.6,-2.1
3D body: height 0.31, standoff 0.01, extent -0.4,-2.4 -0.1,-2.1
3D body: height 0.31, standoff 0.01, extent 0.1,-2.4 0.4,-2.1
3D body: height 0.31, standoff 0.01, extent 0.6,-2.4 0.9,-2.1
3D body: height 0.31, standoff 0.01, extent 1.1,-2.4 1.4,-2.1
3D body: height 0.31, standoff 0.01, extent 1.6,-2.4 1.9,-2.1
3D body: height 0.31, standoff 0.01, extent 2.1,-2.4 2.4,-2.1
3D body: height 0.31, standoff 0.01, extent 2.6,-2.4 2.9,-2.1
3D body: height 0.31, standoff 0.01, extent 3.1,-2.4 3.4,-2.1
3D body: height 0.31, standoff 0.01, extent -3.4,2.1 -3.1,2.4
3D body: height 0.31, standoff 0.01, extent -2.9,2.1 -2.6,2.4
3D body: height 0.31, standoff 0.01, extent -2.4,2.1 -2.1,2.4
3D body: height 0.31, standoff 0.01, extent -1.9,2.1 -1.6,2.4
3D body: height 0.31, standoff 0.01, extent -1.4,2.1 -1.1,2.4
3D body: height 0.31, standoff 0.01, extent -0.9,2.1 -0.6,2.4
3D body: height 0.31, standoff 0.01, extent -0.4,2.1 -0.1,2.4
3D body: height 0.31, standoff 0.01, extent 0.1,2.1 0.4,2.4
3D body: height 0.31, standoff 0.01, extent 0.6,2.1 0.9,2.4
3D body: height 0.31, standoff 0.01, extent 1.1,2.1 1.4,2.4
3D body: height 0.31, standoff 0.01, extent 1.6,2.1 1.9,2.4
3D body: height 0.31, standoff 0.01, extent 2.1,2.1 2.4,2.4
3D body: height 0.31, standoff 0.01, extent 2.6,2.1 2.9,2.4
3D body: height 0.31, standoff 0.01, extent 3.1,2.1 3.4,2.4
3D body: height 0.31, standoff 0.01, extent -3.4,2.6 -3.1,2.9
3D body: height 0.31, standoff 0.01, extent -2.9,2.6 -2.6,2.9
3D body: height 0.31, standoff 0.01, extent -2.4,2.6 -2.1,2.9
3D body: height 0.31, standoff 0.01, extent -1.9,2.6 -1.6,2.9
3D body: height 0.31, standoff 0.01, extent -1.4,2.6 -1.1,2.9
3D body: height 0.31, standoff 0.01, extent -0.9,2.6 -0.6,2.9
3D body: height 0.31, standoff 0.01, extent -0.4,2.6 -0.1,2.9
3D body: height 0.31, standoff 0.01, extent 0.1,2.6 0.4,2.9
3D body: height 0.31, standoff 0.01, extent 0.6,2.6 0.9,2.9
3D body: height 0.31, standoff 0.01, extent 1.1,2.6 1.4,2.9
3D body: height 0.31, standoff 0.01, extent 1.6,2.6 1.9,2.9
3D body: height 0.31, standoff 0.01, extent 2.1,2.6 2.4,2.9
3D body: height 0.31, standoff 0.01, extent 2.6,2.6 2.9,2.9
3D body: height 0.31, standoff 0.01, extent 3.1,2.6 3.4,2.9
3D body: height 0.31, standoff 0.01, extent -3.4,3.1 -3.1,3.4
3D body: height 0.31, standoff 0.01, extent -2.9,3.1 -2.6,3.4
3D body: height 0.31, standoff 0.01, extent -2.4,3.1 -2.1,3.4
3D body: height 0.31, standoff 0.01, extent -1.9,3.1 -1.6,3.4
3D body: height 0.31, standoff 0.01, extent -1.4,3.1 -1.1,3.4
3D body: height 0.31, standoff 0.01, extent -0.9,3.1 -0.6,3.4
3D body: height 0.31, standoff 0.01, extent -0.4,3.1 -0.1,3.4
3D body: height 0.31, standoff 0.01, extent 0.1,3.1 0.4,3.4
3D body: height 0.31, standoff 0.01, extent 0.6,3.1 0.9,3.4
3D body: height 0.31, standoff 0.01, extent 1.1,3.1 1.4,3.4
3D body: height 0.31, standoff 0.01, extent 1.6,3.1 1.9,3.4
3D body: height 0.31, standoff 0.01, extent 2.1,3.1 2.4,3.4
3D body: height 0.31, standoff 0.01, extent 2.6,3.1 2.9,3.4
3D body: height 0.31, standoff 0.01, extent 3.1,3.1 3.4,3.4
3D body: height 0.31, standoff 0.01, extent -3.4,-1.9 -3.1,-1.6
3D body: height 0.31, standoff 0.01, extent -2.9,-1.9 -2.6,-1.6
3D body: height 0.31, standoff 0.01, extent -2.4,-1.9 -2.1,-1.6
3D body: height 0.31, standoff 0.01, extent -1.9,-1.9 -1.6,-1.6
3D body: height 0.31, standoff 0.01, extent 2.1,-1.9 2.4,-1.6
3D body: height 0.31, standoff 0.01, extent 2.6,-1.9 2.9,-1.6
3D body: height 0.31, standoff 0.01, extent 3.1,-1.9 3.4,-1.6
3D body: height 0.31, standoff 0.01, extent -3.4,-1.4 -3.1,-1.1
3D body: height 0.31, standoff 0.01, extent -2.9,-1.4 -2.6,-1.1
3D body: height 0.31, standoff 0.01, extent -2.4,-1.4 -2.1,-1.1
3D body: height 0.31, standoff 0.01, extent 2.1,-1.4 2.4,-1.1
3D body: height 0.31, standoff 0.01, extent 2.6,-1.4 2.9,-1.1
3D body: height 0.31, standoff 0.01, extent 3.1,-1.4 3.4,-1.1
3D body: height 0.31, standoff 0.01, extent -3.4,-0.9 -3.1,-0.6
3D body: height 0.31, standoff 0.01, extent -2.9,-0.9 -2.6,-0.6
3D body: height 0.31, standoff 0.01, extent -2.4,-0.9 -2.1,-0.6
3D body: height 0.31, standoff 0.01, extent 2.1,-0.9 2.4,-0.6
3D body: height 0.31, standoff 0.01, extent 2.6,-0.9 2.9,-0.6
3D body: height 0.31, standoff 0.01, extent 3.1,-0.9 3.4,-0.6
3D body: height 0.31, standoff 0.01, extent -3.4,-0.4 -3.1,-0.1
3D body: height 0.31, standoff 0.01, extent -2.9,-0.4 -2.6,-0.1
3D body: height 0.31, standoff 0.01, extent -2.4,-0.4 -2.1,-0.1
3D body: height 0.31, standoff 0.01, extent 2.1,-0.4 2.4,-0.1
3D body: height 0.31, standoff 0.01, extent 2.6,-0.4 2.9,-0.1
3D body: height 0.31, standoff 0.01, extent 3.1,-0.4 3.4,-0.1
3D body: height 0.31, standoff 0.01, extent -3.4,0.1 -3.1,0.4
3D body: height 0.31, standoff 0.01, extent -2.9,0.1 -2.6,0.4
3D body: height 0.31, standoff 0.01, extent -2.4,0.1 -2.1,0.4
3D body: height 0.31, standoff 0.01, extent 2.1,0.1 2.4,0.4
3D body: height 0.31, standoff 0.01, extent 2.6,0.1 2.9,0.4
3D body: height 0.31, standoff 0.01, extent 3.1,0.1 3.4,0.4
3D body: height 0.31, standoff 0.01, extent -3.4,0.6 -3.1,0.9
3D body: height 0.31, standoff 0.01, extent -2.9,0.6 -2.6,0.9
3D body: height 0.31, standoff 0.01, extent -2.4,0.6 -2.1,0.9
3D body: height 0.31, standoff 0.01, extent 2.1,0.6 2.4,0.9
3D body: height 0.31, standoff 0.01, extent 2.6,0.6 2.9,0.9
3D body: height 0.31, standoff 0.01, extent 3.1,0.6 3.4,0.9
3D body: height 0.31, standoff 0.01, extent -3.4,1.1 -3.1,1.4
3D body: height 0.31, standoff 0.01, extent -2.9,1.1 -2.6,1.4
3D body: height 0.31, standoff 0.01, extent -2.4,1.1 -2.1,1.4
3D body: height 0.31, standoff 0.01, extent 2.1,1.1 2.4,1.4
3D body: height 0.31, standoff 0.01, extent 2.6,1.1 2.9,1.4
3D body: height 0.31, standoff 0.01, extent 3.1,1.1 3.4,1.4
3D body: height 0.31, standoff 0.01, extent -3.4,1.6 -3.1,1.9
3D body: height 0.31, standoff 0.01, extent -2.9,1.6 -2.6,1.9
3D body: height 0.31, standoff 0.01, extent -2.4,1.6 -2.1,1.9
3D body: height 0.31, standoff 0.01, extent 2.1,1.6 2.4,1.9
3D body: height 0.31, standoff 0.01, extent 2.6,1.6 2.9,1.9
3D body: height 0.31, standoff 0.01, extent 3.1,1.6 3.4,1.9
3D body: height 0.81, standoff 0.8, extent -6.25,-5.5 -5.65,-4.9
3D body: height 0.31, standoff 0.01, extent -1.4,-1.4 -1.1,-1.1
3D body: height 0.31, standoff 0.01, extent -0.9,-1.4 -0.6,-1.1
3D body: height 0.31, standoff 0.01, extent -0.4,-1.4 -0.1,-1.1
3D body: height 0.31, standoff 0.01, extent 0.1,-1.4 0.4,-1.1
3D body: height 0.31, standoff 0.01, extent 0.6,-1.4 0.9,-1.1
3D body: height 0.31, standoff 0.01, extent 1.1,-1.4 1.4,-1.1
3D body: height 0.31, standoff 0.01, extent -1.4,1.1 -1.1,1.4
3D body: height 0.31, standoff 0.01, extent -0.9,1.1 -0.6,1.4
3D body: height 0.31, standoff 0.01, extent -0.4,1.1 -0.1,1.4
3D body: height 0.31, standoff 0.01, extent 0.1,1.1 0.4,1.4
3D body: height 0.31, standoff 0.01, extent 0.6,1.1 0.9,1.4
3D body: height 0.31, standoff 0.01, extent 1.1,1.1 1.4,1.4
3D body: height 0.31, standoff 0.01, extent -0.4,-2.4 -0.1,-2.1
3D body: height 0.31, standoff 0.01, extent 0.1,-2.4 0.4,-2.1
3D body: height 0.31, standoff 0.01, extent 0.6,-2.4 0.9,-2.1
3D body: height 0.31, standoff 0.01, extent 1.1,-2.4 1.4,-2.1
3D body: height 0.31, standoff 0.01, extent 1.6,-2.4 1.9,-2.1
3D body: height 0.31, standoff 0.01, extent 2.1,-2.4 2.4,-2.1
3D body: height 0.31, standoff 0.01, extent -1.4,-0.9 -1.1,-0.6
3D body: height 0.31, standoff 0.01, extent -1.4,-0.4 -1.1,-0.1
3D body: height 0.31, standoff 0.01, extent -1.4,0.1 -1.1,0.4
3D body: height 0.31, standoff 0.01, extent -1.4,0.6 -1.1,0.9
3D body: height 0.31, standoff 0.01, extent 2.1,-2.4 2.4,-2.1
3D body: height 0.31, standoff 0.01, extent 2.6,-2.4 2.9,-2.1
3D body: height 0.31, standoff 0.01, extent 3.1,-2.4 3.4,-2.1
3D body: height 0.31, standoff 0.01, extent 3.6,-2.4 3.9,-2.1
3D body: height 0.31, standoff 0.01, extent 4.1,-2.4 4.4,-2.1
3D body: height 0.31, standoff 0.01, extent 4.6,-2.4 4.9,-2.1
3D body: height 0.31, standoff 0.01, extent 1.1,-0.9 1.4,-0.6
3D body: height 0.31, standoff 0.01, extent 1.1,-0.4 1.4,-0.1
3D body: height 0.31, standoff 0.01, extent 1.1,0.1 1.4,0.4
3D body: height 0.31, standoff 0.01, extent 1.1,0.6 1.4,0.9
